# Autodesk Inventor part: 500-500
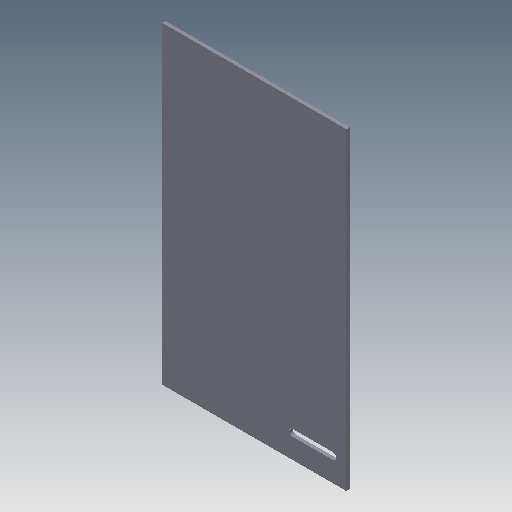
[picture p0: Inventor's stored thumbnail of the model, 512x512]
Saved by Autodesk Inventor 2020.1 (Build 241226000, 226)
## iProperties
Created: 2010-10
Part Number: 500-500
Document SubType Name: Modeling
Designer: F.Stasiak
Density: 0.55 g/cm^3
Material: MDF
Description: =Drzwiczki z otworem <d0> x <d9>
Mass: 2785.99 g
Surface Area: 10456.7 cm^2
Volume: 5065.43 cm^3
Appearance: Mleczny
Company: Fabian Stasiak CAD Consulting
Manager: www.cadconsulting.pl
d0: 547
d9: 931
Author: F.Stasiak
Subject: Zbiór ćwiczeń. Autodesk Inventor 2020. Kurs podstawowy
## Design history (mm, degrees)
sketch "Szkic1"
  geometry: L1 (0, 0)-(547, 0); L2 (547, 0)-(547, 931); L3 (547, 931)-(0, 931); L4 (0, 931)-(0, 0)
  constraints: 8 end point, 2 parallel, 1 horizontal, 1 perpendicular
  dimensions: "d0" = 547 distance of L2.end L3.end; "d9" = 931 distance of L1.end L2.end (derived)
extrude "Wyciągnięcie proste1" new body sketch "Szkic1" distance "d1" = 10; taper "d2" = 0 deg
sketch "Szkic2"
  geometry: L1 (387, 60)-(507, 60); L2 (507, 80)-(387, 80); L3 (547, 0)-(0, 0) reference; L4 (547, 931)-(547, 0) reference; A1 r 10 centre (507, 70) between (507, 60) and (507, 80); A2 r 10 centre (387, 70) between (387, 80) and (387, 60)
  constraints: 4 end point, 4 point on circle, 4 tangent, 2 centre point, 1 horizontal, 1 parallel
  dimensions: "d3" = 10 radius of A1; "d4" = 120 distance of L1.start L1.end; "d5" = 60 distance between parallel lines of L3 L1; "d6" = 40 distance from line of L4 A1.centre
extrude "Wyciągnięcie proste2" cut sketch "Szkic2" extent not by distance; stored distance "d7" = 10; taper "d8" = 0 deg
node "Bryła1"
